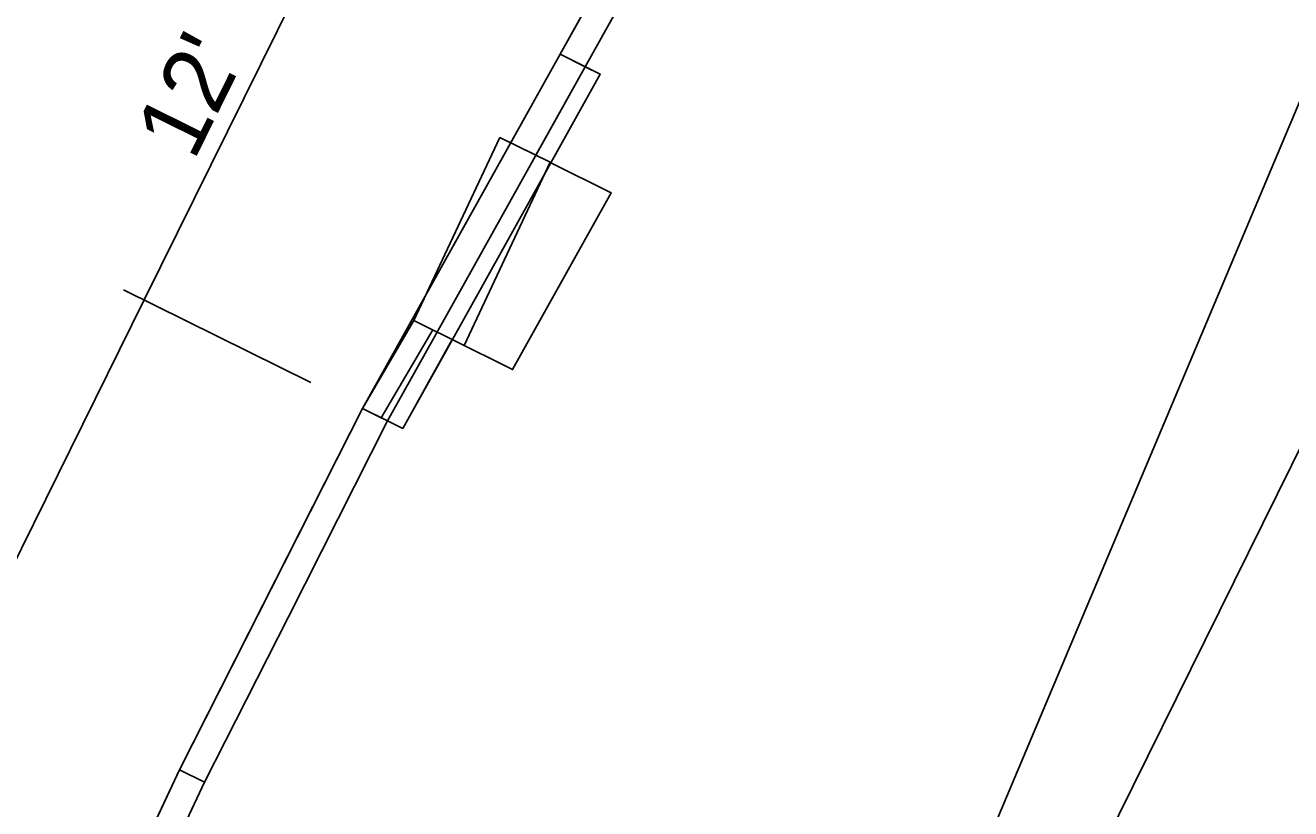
# Model space of a CAD drawing. Extents: x 14104283 to 14128447, y 8633203 to 8671666.
# Drawn here: x 14118493.4 to 14118643.5, y 8668473.9 to 8668566.9 of the extents above; entities that cross this region are included whole.
import ezdxf

# ---------------------------------------------------------------- set-up
doc = ezdxf.new("R2010")
doc.units = 0
for name, color, linetype in [('Default', 7, 'Continuous'), ('dsnNonPlotable', 7, 'Continuous'), ('dsnShadingPaved', 7, 'Continuous'), ('dsnStgShadingPrevPav', 7, 'Continuous'), ('dsnTextFinalPlan', 7, 'Continuous'), ('TC_Subbase', 7, 'Continuous'), ('TC_SubgradeTreatment', 7, 'Continuous'), ('TC_SubstrataExistingPavement', 7, 'Continuous'), ('Terrain', 7, 'Continuous')]:
    doc.layers.add(name, color=color, linetype=linetype)

msp = doc.modelspace()

# ---------------------------------------------------------------- linework, layer by layer
at = {"layer": 'Default'}
for p, q in [((14118556.81, 8668563.44), (14118559.8, 8668561.96)), ((14118536.35, 8668519.93), (14118533.36, 8668521.41))]:
    msp.add_line(p, q, dxfattribs=at)
for points in [[(14118533.36, 8668521.41), (14118542.5, 8668537.78), (14118556.81, 8668563.44)], [(14118536.35, 8668519.93), (14118545.48, 8668536.3), (14118559.8, 8668561.96)]]:
    msp.add_lwpolyline(points, dxfattribs=at)
at = {"layer": 'dsnNonPlotable'}
msp.add_lwpolyline([(14118056.48, 8667161.91), (14118665.06, 8668606.45), (14119130.44, 8668410.38), (14118521.87, 8666965.84)], close=True, dxfattribs=at)
at = {"layer": 'dsnShadingPaved'}
msp.add_lwpolyline([(14118533.36, 8668521.41), (14118556.81, 8668563.44), (14118561.59, 8668561.08), (14118555.74, 8668550.58), (14118562.89, 8668547), (14118551.18, 8668526.02), (14118544.03, 8668529.6), (14118538.14, 8668519.04)], close=True, dxfattribs=at)
at = {"layer": 'dsnStgShadingPrevPav'}
for points in [[(14118556.81, 8668563.44), (14118568.52, 8668584.42), (14118571.5, 8668582.95), (14118559.8, 8668561.96)], [(14118511.64, 8668478.53), (14118511.64, 8668478.53), (14118533.36, 8668521.41), (14118536.35, 8668519.93), (14118524.58, 8668496.7), (14118514.63, 8668477.06), (14118514.63, 8668477.06)], [(14118496.01, 8668445.27), (14118511.64, 8668478.53), (14118514.63, 8668477.06), (14118499, 8668443.79)]]:
    msp.add_lwpolyline(points, close=True, dxfattribs=at)
at = {"layer": 'dsnTextFinalPlan'}
for p, q in [((14118507.46, 8668534.29), (14118528.74, 8668577.32)), ((14118505.01, 8668535.5), (14118527.24, 8668524.51)), ((14118461.94, 8668442.22), (14118507.46, 8668534.29))]:
    msp.add_line(p, q, dxfattribs=at)
msp.add_lwpolyline([(14118092.03, 8667853.71), (14118606.59, 8668894.44), (14118787.23, 8668805.14), (14118272.66, 8667764.4)], close=True, dxfattribs=at)
at = {"layer": 'TC_Subbase'}
for p, q in [((14118561.59, 8668561.08), (14118559.8, 8668561.96)), ((14118538.14, 8668519.04), (14118536.35, 8668519.93))]:
    msp.add_line(p, q, dxfattribs=at)
msp.add_lwpolyline([(14118538.14, 8668519.04), (14118547.28, 8668535.42), (14118561.59, 8668561.08)], dxfattribs=at)
at = {"layer": 'TC_SubgradeTreatment'}
for p, q in [((14118562.89, 8668547), (14118555.74, 8668550.58)), ((14118551.18, 8668526.02), (14118544.03, 8668529.6))]:
    msp.add_line(p, q, dxfattribs=at)
msp.add_lwpolyline([(14118551.18, 8668526.02), (14118554.43, 8668531.84), (14118562.89, 8668547)], dxfattribs=at)
at = {"layer": 'TC_SubstrataExistingPavement'}
for p, q in [((14118556.81, 8668563.44), (14118559.8, 8668561.96)), ((14118555.65, 8668550.63), (14118549.67, 8668553.58)), ((14118535.6, 8668520.3), (14118541.71, 8668530.75)), ((14118536.35, 8668519.93), (14118533.36, 8668521.41))]:
    msp.add_line(p, q, dxfattribs=at)
for points in [[(14118559.8, 8668561.96), (14118576.44, 8668591.8), (14118583.24, 8668603.98), (14118602.77, 8668639)], [(14118539.47, 8668531.85), (14118545.45, 8668528.9), (14118550.55, 8668539.76), (14118555.65, 8668550.63)], [(14118514.63, 8668477.06), (14118524.58, 8668496.7), (14118536.35, 8668519.93)], [(14118511.64, 8668478.53), (14118514.63, 8668477.06), (14118458.17, 8668356.88), (14118455.18, 8668358.36)]]:
    msp.add_lwpolyline(points, dxfattribs=at)
at = {"layer": 'Terrain'}
for p, q in [((14118559.8, 8668561.96), (14118556.81, 8668563.44)), ((14118553.94, 8668551.46), (14118559.8, 8668561.96)), ((14118549.67, 8668553.58), (14118553.94, 8668551.47)), ((14118533.36, 8668521.41), (14118539.47, 8668531.85)), ((14118455.18, 8668358.36), (14118511.64, 8668478.53))]:
    msp.add_line(p, q, dxfattribs=at)
for points in [[(14118556.81, 8668563.44), (14118573.45, 8668593.27), (14118580.25, 8668605.46), (14118599.79, 8668640.48)], [(14118539.47, 8668531.85), (14118540.07, 8668533.13), (14118549.67, 8668553.58)], [(14118511.64, 8668478.53), (14118521.59, 8668498.17), (14118533.36, 8668521.41)]]:
    msp.add_lwpolyline(points, dxfattribs=at)

# ---------------------------------------------------------------- texts
at = {"layer": 'dsnTextFinalPlan'}
msp.add_text("12'", height=8, rotation=63.6911, dxfattribs=at).set_placement((14118513.34, 8668550.66))

doc.saveas('drawing.dxf')
